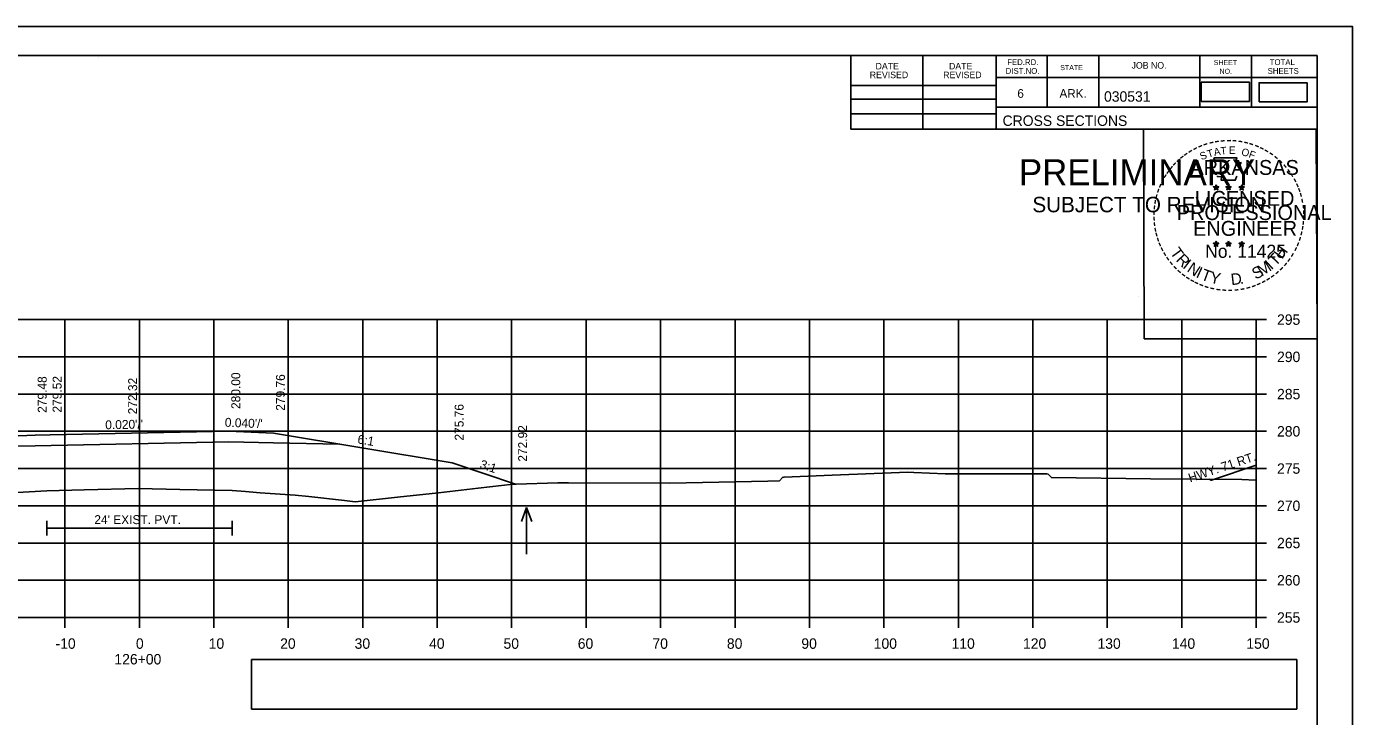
# Model space of a CAD drawing. Extents: x 285 to 4233, y -659 to 3710.
# Drawn here: x 524.1 to 702.2, y 1376.9 to 1469.5 of the extents above; entities that cross this region are included whole.
import ezdxf

# ---------------------------------------------------------------- set-up
doc = ezdxf.new("R2010")
doc.units = 0
for name, color, linetype in [('R_Alt Surface', 7, 'Continuous'), ('R_Axis', 7, 'Continuous'), ('R_Axis Annot', 7, 'Continuous'), ('R_Border', 7, 'Continuous'), ('R_Border PE', 7, 'Continuous'), ('R_Border Prem', 7, 'Continuous'), ('R_Exist Surface', 7, 'Continuous'), ('R_Fin Surface', 7, 'Continuous'), ('R_Grid', 7, 'Continuous'), ('R_No Plot', 7, 'Continuous'), ('R_Proposed Const Limits', 7, 'Continuous'), ('R_Water', 7, 'Continuous'), ('R_Water Annot', 7, 'Continuous'), ('R_Xsect Elev', 7, 'Continuous'), ('R_Xsect Slope', 7, 'Continuous')]:
    doc.layers.add(name, color=color, linetype=linetype)

msp = doc.modelspace()

# ---------------------------------------------------------------- linework, layer by layer
at = {"layer": 'R_Alt Surface'}
for points in [[(508.71, 1412.91), (517.28, 1413.08), (525.28, 1413.24), (551.28, 1413.76), (551.28, 1413.76), (557.28, 1413.64), (566.12, 1413.47)], [(526.85, 1403.17), (526.85, 1401.17)], [(526.85, 1402.17), (551.74, 1402.17)], [(551.74, 1403.17), (551.74, 1401.17)]]:
    msp.add_lwpolyline(points, dxfattribs=at)
at = {"layer": 'R_Axis'}
for p, q in [((689.28, 1390.18), (689.28, 1430.18)), ((690.68, 1430.18), (689.28, 1430.18)), ((690.68, 1425.18), (689.28, 1425.18)), ((690.68, 1420.18), (689.28, 1420.18)), ((690.68, 1415.18), (689.28, 1415.18)), ((690.68, 1410.18), (689.28, 1410.18)), ((690.68, 1405.18), (689.28, 1405.18)), ((690.68, 1400.18), (689.28, 1400.18)), ((690.68, 1395.18), (689.28, 1395.18)), ((389.28, 1390.18), (689.28, 1390.18)), ((529.28, 1388.78), (529.28, 1390.18)), ((539.28, 1388.78), (539.28, 1390.18)), ((549.28, 1388.78), (549.28, 1390.18)), ((559.28, 1388.78), (559.28, 1390.18)), ((569.28, 1388.78), (569.28, 1390.18)), ((579.28, 1388.78), (579.28, 1390.18)), ((589.28, 1388.78), (589.28, 1390.18)), ((599.28, 1388.78), (599.28, 1390.18)), ((609.28, 1388.78), (609.28, 1390.18)), ((619.28, 1388.78), (619.28, 1390.18)), ((629.28, 1388.78), (629.28, 1390.18)), ((639.28, 1388.78), (639.28, 1390.18)), ((649.28, 1388.78), (649.28, 1390.18)), ((659.28, 1388.78), (659.28, 1390.18)), ((669.28, 1388.78), (669.28, 1390.18)), ((679.28, 1388.78), (679.28, 1390.18)), ((689.28, 1388.78), (689.28, 1390.18)), ((690.68, 1390.18), (689.28, 1390.18))]:
    msp.add_line(p, q, dxfattribs=at)
at = {"layer": 'R_Axis Annot'}
for points in [[(681.91, 1459.49), (688.36, 1459.49), (688.36, 1462.05), (681.91, 1462.05)], [(689.66, 1459.42), (696.12, 1459.42), (696.12, 1461.98), (689.66, 1461.98)], [(554.36, 1377.88), (694.72, 1377.88), (694.72, 1384.53), (554.36, 1384.53)]]:
    msp.add_lwpolyline(points, close=True, dxfattribs=at)
at = {"layer": 'R_Border'}
for p, q in [((381.28, 1465.64), (697.46, 1465.64)), ((533.8, 1465.38), (533.8, 1465.38)), ((533.8, 1465.38), (533.8, 1465.38)), ((634.82, 1455.76), (634.82, 1465.64)), ((644.5, 1455.76), (644.5, 1465.64)), ((654.36, 1465.64), (654.36, 1455.76)), ((661.2, 1465.64), (661.2, 1458.7)), ((668.14, 1465.64), (668.14, 1458.7)), ((681.72, 1465.64), (681.72, 1458.7)), ((688.66, 1465.64), (688.66, 1458.7)), ((697.46, 1260.18), (697.46, 1465.64)), ((697.46, 1462.7), (654.36, 1462.7)), ((697.46, 1462.72), (697.46, 1462.72)), ((634.82, 1461.62), (654.36, 1461.62)), ((634.82, 1459.76), (654.36, 1459.76)), ((697.46, 1458.7), (654.36, 1458.7)), ((657.32, 1458.7), (697.46, 1458.7)), ((634.82, 1457.82), (654.36, 1457.82)), ((697.46, 1455.76), (634.82, 1455.76))]:
    msp.add_line(p, q, dxfattribs=at)
at = {"layer": 'R_Border PE'}
for p, q in [((683.54, 1448.02), (683.89, 1447.9)), ((683.54, 1448.02), (683.8, 1447.97)), ((683.54, 1448.02), (683.78, 1447.89)), ((683.68, 1447.61), (683.89, 1447.9)), ((683.68, 1447.61), (683.8, 1447.85)), ((683.89, 1448.27), (683.85, 1448.02)), ((683.89, 1447.9), (683.89, 1448.27)), ((683.89, 1448.27), (683.94, 1448.02)), ((684.24, 1448.02), (683.89, 1447.9)), ((684.11, 1447.61), (683.89, 1447.9)), ((684.24, 1448.02), (683.95, 1447.97)), ((684.11, 1447.61), (683.97, 1447.9)), ((684.24, 1448.02), (684.04, 1447.91)), ((685.21, 1448.02), (685.56, 1447.9)), ((685.21, 1448.02), (685.47, 1447.97)), ((685.21, 1448.02), (685.45, 1447.89)), ((685.35, 1447.61), (685.56, 1447.9)), ((685.35, 1447.61), (685.47, 1447.85)), ((685.56, 1448.27), (685.52, 1448.02)), ((685.56, 1447.9), (685.56, 1448.27)), ((685.56, 1448.27), (685.61, 1448.02)), ((685.91, 1448.02), (685.56, 1447.9)), ((685.78, 1447.61), (685.56, 1447.9)), ((685.91, 1448.02), (685.62, 1447.97)), ((685.78, 1447.61), (685.64, 1447.9)), ((685.91, 1448.02), (685.71, 1447.91)), ((686.98, 1448), (687.33, 1447.89)), ((686.98, 1448), (687.23, 1447.96)), ((686.98, 1448), (687.22, 1447.88)), ((687.11, 1447.6), (687.33, 1447.89)), ((687.33, 1448.26), (687.29, 1448.01)), ((687.33, 1447.89), (687.33, 1448.26)), ((687.33, 1448.26), (687.38, 1448.01)), ((687.67, 1448), (687.33, 1447.89)), ((687.54, 1447.6), (687.33, 1447.89)), ((687.67, 1448), (687.39, 1447.95)), ((687.54, 1447.6), (687.4, 1447.89)), ((687.67, 1448), (687.47, 1447.9)), ((683.68, 1447.61), (683.89, 1447.82)), ((684.11, 1447.61), (683.89, 1447.82)), ((685.35, 1447.61), (685.56, 1447.82)), ((685.78, 1447.61), (685.56, 1447.82)), ((687.11, 1447.6), (687.24, 1447.84)), ((687.11, 1447.6), (687.33, 1447.81)), ((687.54, 1447.6), (687.33, 1447.81)), ((683.54, 1440.44), (683.89, 1440.33)), ((683.54, 1440.44), (683.79, 1440.4)), ((683.54, 1440.44), (683.78, 1440.32)), ((683.67, 1440.03), (683.89, 1440.33)), ((683.67, 1440.03), (683.8, 1440.28)), ((683.67, 1440.03), (683.89, 1440.25)), ((683.89, 1440.7), (683.85, 1440.44)), ((683.89, 1440.33), (683.89, 1440.7)), ((683.89, 1440.7), (683.94, 1440.45)), ((684.24, 1440.44), (683.89, 1440.33)), ((684.1, 1440.03), (683.89, 1440.33)), ((684.1, 1440.03), (683.89, 1440.25)), ((684.24, 1440.44), (683.95, 1440.39)), ((684.1, 1440.03), (683.97, 1440.33)), ((684.24, 1440.44), (684.03, 1440.34)), ((685.21, 1440.44), (685.56, 1440.33)), ((685.21, 1440.44), (685.46, 1440.4)), ((685.21, 1440.44), (685.45, 1440.32)), ((685.34, 1440.03), (685.56, 1440.33)), ((685.34, 1440.03), (685.47, 1440.28)), ((685.34, 1440.03), (685.56, 1440.25)), ((685.56, 1440.7), (685.52, 1440.44)), ((685.56, 1440.33), (685.56, 1440.7)), ((685.56, 1440.7), (685.61, 1440.45)), ((685.91, 1440.44), (685.56, 1440.33)), ((685.77, 1440.03), (685.56, 1440.33)), ((685.77, 1440.03), (685.56, 1440.25)), ((685.91, 1440.44), (685.62, 1440.39)), ((685.77, 1440.03), (685.63, 1440.33)), ((685.91, 1440.44), (685.7, 1440.34)), ((686.98, 1440.43), (687.33, 1440.32)), ((686.98, 1440.43), (687.23, 1440.39)), ((686.98, 1440.43), (687.21, 1440.31)), ((687.11, 1440.02), (687.33, 1440.32)), ((687.11, 1440.02), (687.24, 1440.27)), ((687.11, 1440.02), (687.32, 1440.24)), ((687.33, 1440.69), (687.28, 1440.43)), ((687.54, 1440.02), (687.32, 1440.24)), ((687.33, 1440.32), (687.33, 1440.69)), ((687.33, 1440.69), (687.37, 1440.44)), ((687.67, 1440.43), (687.33, 1440.32)), ((687.54, 1440.02), (687.33, 1440.32)), ((687.67, 1440.43), (687.39, 1440.38)), ((687.54, 1440.02), (687.4, 1440.32)), ((687.67, 1440.43), (687.47, 1440.33))]:
    msp.add_line(p, q, dxfattribs=at)
for points in [[(683.59, 1451.89), (683.85, 1451.07)], [(687.1, 1450.97), (687.24, 1451.26), (686.55, 1451.23), (686.7, 1451.89), (683.59, 1451.89)], [(683.89, 1448.27), (684.11, 1447.61), (683.54, 1448.02), (684.24, 1448.02), (683.68, 1447.61), (683.89, 1448.27)], [(684.08, 1449.47), (684.08, 1449.38), (684.64, 1449.36), (684.59, 1448.89), (686.46, 1448.89), (686.66, 1449.43)], [(685.56, 1448.27), (685.78, 1447.61), (685.21, 1448.02), (685.91, 1448.02), (685.35, 1447.61), (685.56, 1448.27)], [(687.33, 1448.26), (687.54, 1447.6), (686.98, 1448), (687.67, 1448), (687.11, 1447.6), (687.33, 1448.26)], [(683.89, 1440.7), (684.1, 1440.03), (683.54, 1440.44), (684.24, 1440.44), (683.67, 1440.03), (683.89, 1440.7)], [(685.56, 1440.7), (685.77, 1440.03), (685.21, 1440.44), (685.91, 1440.44), (685.34, 1440.03), (685.56, 1440.7)], [(687.33, 1440.69), (687.54, 1440.02), (686.98, 1440.43), (687.67, 1440.43), (687.11, 1440.02), (687.33, 1440.69)]]:
    msp.add_lwpolyline(points, dxfattribs=at)
for centre, radius in [((683.89, 1447.9), 0.172), ((683.89, 1447.9), 0.145), ((683.89, 1447.9), 0.116), ((683.89, 1447.9), 0.0991), ((683.89, 1447.9), 0.0747), ((683.89, 1447.9), 0.0495), ((683.89, 1447.9), 0.0296), ((685.56, 1447.9), 0.172), ((685.56, 1447.9), 0.145), ((685.56, 1447.9), 0.116), ((685.56, 1447.9), 0.0991), ((685.56, 1447.9), 0.0747), ((685.56, 1447.9), 0.0495), ((685.56, 1447.9), 0.0296), ((687.33, 1447.89), 0.172), ((687.33, 1447.89), 0.145), ((687.33, 1447.89), 0.116), ((687.33, 1447.89), 0.0991), ((687.33, 1447.89), 0.0747), ((687.33, 1447.89), 0.0495), ((687.33, 1447.89), 0.0296), ((683.89, 1440.33), 0.172), ((683.89, 1440.33), 0.145), ((683.89, 1440.33), 0.116), ((683.89, 1440.33), 0.0991), ((683.89, 1440.33), 0.0747), ((683.89, 1440.33), 0.0495), ((683.89, 1440.33), 0.0296), ((685.56, 1440.33), 0.172), ((685.56, 1440.33), 0.145), ((685.56, 1440.33), 0.116), ((685.56, 1440.33), 0.0991), ((685.56, 1440.33), 0.0747), ((685.56, 1440.33), 0.0495), ((685.56, 1440.33), 0.0296), ((687.32, 1440.32), 0.172), ((687.32, 1440.32), 0.145), ((687.32, 1440.32), 0.116), ((687.32, 1440.32), 0.0991), ((687.32, 1440.32), 0.0747), ((687.32, 1440.32), 0.0495), ((687.32, 1440.32), 0.0296)]:
    msp.add_circle(centre, radius, dxfattribs=at)
at = {"layer": 'R_Exist Surface'}
msp.add_lwpolyline([(521.32, 1406.88), (526.85, 1407.17), (531.87, 1407.31), (539.17, 1407.51), (544.72, 1407.39), (551.74, 1407.24), (553.52, 1407.1), (555.5, 1406.94), (560.21, 1406.59), (562.06, 1406.42), (566.84, 1405.87), (568.25, 1405.7), (573.96, 1406.33), (579.47, 1406.93), (584.8, 1407.55), (589.47, 1408.09), (589.89, 1408.1), (595.49, 1408.26), (596.92, 1408.25), (610.53, 1408.23), (623.67, 1408.49), (625.25, 1408.52), (625.27, 1408.55), (625.65, 1408.99), (625.86, 1409.04), (625.89, 1409.04), (632.34, 1409.29), (642.5, 1409.68), (643.31, 1409.65), (647.51, 1409.49), (660.23, 1409.47), (661.13, 1409.47), (661.16, 1409.47), (661.36, 1409.41), (661.64, 1409.1), (661.77, 1408.97), (675.1, 1408.82), (687.37, 1408.69), (689.17, 1408.63), (689.28, 1408.63)], dxfattribs=at)
at = {"layer": 'R_Fin Surface'}
for points in [[(469.1, 1404.15), (472.9, 1402.88), (497.28, 1411.01), (517.28, 1414.34), (525.28, 1414.66), (527.28, 1414.7), (551.28, 1415.18), (557.28, 1414.94), (581.28, 1410.94), (589.81, 1408.1)], [(682.97, 1408.74), (683.25, 1408.64), (683.27, 1408.64), (689.28, 1410.64)]]:
    msp.add_lwpolyline(points, dxfattribs=at)
at = {"layer": 'R_Grid'}
for p, q in [((389.28, 1430.18), (689.28, 1430.18)), ((529.28, 1390.18), (529.28, 1430.18)), ((539.28, 1390.18), (539.28, 1430.18)), ((549.28, 1390.18), (549.28, 1430.18)), ((559.28, 1390.18), (559.28, 1430.18)), ((569.28, 1390.18), (569.28, 1430.18)), ((579.28, 1390.18), (579.28, 1430.18)), ((589.28, 1390.18), (589.28, 1430.18)), ((599.28, 1390.18), (599.28, 1430.18)), ((609.28, 1390.18), (609.28, 1430.18)), ((619.28, 1390.18), (619.28, 1430.18)), ((629.28, 1390.18), (629.28, 1430.18)), ((639.28, 1390.18), (639.28, 1430.18)), ((649.28, 1390.18), (649.28, 1430.18)), ((659.28, 1390.18), (659.28, 1430.18)), ((669.28, 1390.18), (669.28, 1430.18)), ((679.28, 1390.18), (679.28, 1430.18)), ((689.28, 1390.18), (689.28, 1430.18)), ((389.28, 1425.18), (689.28, 1425.18)), ((389.28, 1420.18), (689.28, 1420.18)), ((389.28, 1415.18), (689.28, 1415.18)), ((389.28, 1410.18), (689.28, 1410.18)), ((389.28, 1405.18), (689.28, 1405.18)), ((389.28, 1400.18), (689.28, 1400.18)), ((389.28, 1395.18), (689.28, 1395.18)), ((389.28, 1390.18), (689.28, 1390.18))]:
    msp.add_line(p, q, dxfattribs=at)
at = {"layer": 'R_No Plot'}
for p, q in [((368.88, 1469.54), (702.21, 1469.54)), ((673.49, 1433.3), (673.49, 1433.3))]:
    msp.add_line(p, q, dxfattribs=at)
for points in [[(368.87, 1469.54), (702.21, 1469.54), (702.21, 1256.2), (368.87, 1256.2)], [(615.2, 1465.64), (634.82, 1465.64), (634.82, 1455.76), (650.93, 1455.76), (674.13, 1455.76), (674.25, 1427.6), (697.46, 1427.6), (697.46, 1260.18), (381.28, 1260.18), (381.28, 1465.64)], [(674.13, 1455.76), (697.34, 1455.76), (697.46, 1427.6), (674.25, 1427.6)]]:
    msp.add_lwpolyline(points, close=True, dxfattribs=at)
at = {"layer": 'R_Proposed Const Limits'}
for points in [[(527.28, 1414.7), (527.28, 1414.7), (527.28, 1414.7)], [(551.28, 1415.18), (551.28, 1415.18), (551.28, 1415.18)], [(589.82, 1408.09), (589.81, 1408.1), (589.8, 1408.1), (589.79, 1408.1)]]:
    msp.add_lwpolyline(points, dxfattribs=at)
at = {"layer": 'R_Water Annot'}
for p, q in [((591.29, 1404.97), (590.59, 1403.05)), ((591.29, 1398.69), (591.29, 1404.97)), ((591.29, 1404.97), (591.99, 1403.05))]:
    msp.add_line(p, q, dxfattribs=at)
at = {"layer": 'R_Xsect Elev'}
msp.add_line((539.28, 1407.5), (539.28, 1423.25), dxfattribs=at)

# ---------------------------------------------------------------- texts
at = {"layer": 'R_Axis Annot'}
for s, p in [('295', (692.08, 1429.48)), ('290', (692.08, 1424.48)), ('285', (692.08, 1419.48)), ('280', (692.08, 1414.48)), ('275', (692.08, 1409.48)), ('270', (692.08, 1404.48)), ('265', (692.08, 1399.48)), ('260', (692.08, 1394.48)), ('255', (692.08, 1389.48)), ('-10', (528.02, 1385.98)), ('0', (538.82, 1385.98)), ('10', (548.59, 1385.98)), ('20', (558.19, 1385.98)), ('30', (568.19, 1385.98)), ('40', (578.19, 1385.98)), ('50', (588.19, 1385.98)), ('60', (598.16, 1385.98)), ('70', (608.19, 1385.98)), ('80', (618.19, 1385.98)), ('90', (628.19, 1385.98)), ('100', (637.91, 1385.98)), ('110', (648.36, 1385.98)), ('120', (657.96, 1385.98)), ('130', (667.96, 1385.98)), ('140', (677.96, 1385.98)), ('150', (687.96, 1385.98)), ('126+00', (535.93, 1383.88))]:
    msp.add_text(s, height=1.4, dxfattribs=at).set_placement(p)
at = {"layer": 'R_Border'}
for s, height, p in [('DATE', 0.879, (638.16, 1463.78)), ('DATE', 0.879, (648.02, 1463.78)), ('DIST.NO.', 0.782, (655.64, 1463.18)), ('FED.RD.', 0.782, (655.84, 1464.36)), ('STATE', 0.684, (662.96, 1463.68)), ('JOB NO.', 0.879, (672.54, 1463.88)), ('SHEET', 0.684, (683.58, 1464.36)), ('SHEETS', 0.782, (690.82, 1463.18)), ('TOTAL', 0.782, (691.1, 1464.36)), ('REVISED', 0.879, (637.38, 1462.6)), ('REVISED', 0.879, (647.24, 1462.6)), ('NO.', 0.684, (684.36, 1463.18)), ('6', 1.17, (657.2, 1459.96)), ('ARK.', 1.172, (662.86, 1459.96)), ('030531', 1.4, (668.84, 1459.44)), ('CROSS SECTIONS', 1.4, (655.22, 1456.19))]:
    msp.add_text(s, height=height, rotation=360, dxfattribs=at).set_placement(p)
at = {"layer": 'R_Border PE'}
for s, height, rotation, p in [('-', 1.6, 28.7918, (681.07, 1452.43)), ('-', 1.6, 24.3072, (681.7, 1452.75)), ('-', 1.6, 19.1761, (682.33, 1453.02)), ('-', 1.6, 13.6301, (683.08, 1453.26)), ('A', 1, 11.2132, (683.68, 1452.15)), ('-', 1.6, 10.2193, (683.76, 1453.42)), ('T', 1, 6.0228, (684.53, 1452.32)), ('-', 1.6, 5.8968, (684.49, 1453.53)), ('-', 1.6, 0.1862, (685.26, 1453.61)), ('E', 1, 0.8323, (685.63, 1452.43)), ('-', 1.6, 357.743, (685.98, 1453.59)), ('-', 1.6, 352.1617, (686.73, 1453.54)), ('-', 1.6, 347.2049, (687.45, 1453.42)), ('-', 1.6, 342.3362, (688.08, 1453.27)), ('-', 1.6, 337.8551, (688.82, 1453.04)), ('-', 1.6, 334.1211, (689.45, 1452.77)), ('-', 1.6, 42.9622, (678.98, 1450.87)), ('-', 1.6, 38.9507, (679.41, 1451.29)), ('-', 1.6, 36.2317, (679.89, 1451.67)), ('-', 1.6, 34.0636, (680.47, 1452.06)), ('ARKANSAS', 2, 360, (680.44, 1449.61)), ('S', 1, 21.594, (681.94, 1451.57)), ('T', 1, 16.4036, (682.85, 1451.9)), ('O', 1, 350.4515, (687.24, 1452.22)), ('F', 1, 340.0707, (688.19, 1451.99)), ('-', 1.6, 329.6409, (690.03, 1452.49)), ('-', 1.6, 325.8627, (690.67, 1452.13)), ('-', 1.6, 320.5297, (691.28, 1451.7)), ('-', 1.6, 315.5786, (691.88, 1451.22)), ('-', 1.6, 58.0706, (677.39, 1448.82)), ('-', 1.6, 54.2325, (677.72, 1449.34)), ('-', 1.6, 50.6142, (678.13, 1449.91)), ('-', 1.6, 48.423, (678.53, 1450.4)), ('-', 1.6, 309.8797, (692.45, 1450.67)), ('-', 1.6, 306.6522, (692.97, 1450.06)), ('-', 1.4, 303.6753, (693.46, 1449.5)), ('-', 1.6, 67.7743, (676.82, 1447.59)), ('-', 1.6, 62.8713, (677.08, 1448.2)), ('DWB', 0.01, 360, (683.88, 1447.9)), ('DWB', 0.01, 360, (685.55, 1447.9)), ('DWB', 0.01, 360, (687.31, 1447.89)), ('-', 1.6, 299.6684, (693.78, 1448.89)), ('-', 1.6, 294.6628, (694.1, 1448.28)), ('-', 1.6, 290.5728, (694.36, 1447.7)), ('-', 1.6, 81.2013, (676.27, 1445.53)), ('-', 1.6, 75.461, (676.4, 1446.25)), ('-', 1.6, 72.3945, (676.6, 1446.96)), ('LICENSED', 2, 360, (681.04, 1445.46)), ('-', 1.6, 285.1233, (694.59, 1447.12)), ('-', 1.6, 280.5493, (694.79, 1446.38)), ('-', 1.6, 89.0622, (676.17, 1444.14)), ('-', 1.6, 85.1863, (676.2, 1444.84)), ('PROFESSIONAL', 2, 360, (678.61, 1443.55)), ('-', 1.6, 276.5962, (694.96, 1445.61)), ('-', 1.6, 274.3301, (695.02, 1444.89)), ('-', 1.6, 94.1959, (676.21, 1443.42)), ('-', 1.6, 98.9479, (676.28, 1442.75)), ('-', 1.6, 101.7149, (676.41, 1442.02)), ('ENGINEER', 2, 360, (680.8, 1441.43)), ('-', 1.6, 260.9953, (694.96, 1442.94)), ('-', 1.6, 263.5172, (695.03, 1443.59)), ('-', 1.6, 269.9407, (695.05, 1444.26)), ('-', 1.6, 105.4578, (676.58, 1441.42)), ('-', 1.6, 109.0874, (676.79, 1440.79)), ('-', 1.6, 252.8681, (694.67, 1441.54)), ('-', 1.6, 255.7626, (694.85, 1442.26)), ('-', 1.6, 114.0643, (677.04, 1440.2)), ('-', 1.6, 115.7289, (677.35, 1439.58)), ('-', 1.6, 120.4471, (677.71, 1438.99)), ('T', 1.54, 306.0406, (677.65, 1439.17)), ('R', 1.54, 314.005, (678.41, 1438.12)), ('No. 11425', 1.757, 360, (682.43, 1438.48)), ('DWB', 0.01, 360, (683.88, 1440.33)), ('DWB', 0.01, 360, (685.55, 1440.33)), ('DWB', 0.01, 360, (687.31, 1440.32)), ('T', 1.54, 46.6444, (691.88, 1437.26)), ('H', 1.54, 54.6088, (692.77, 1438.2)), ('-', 1.6, 239.0712, (693.79, 1439.48)), ('-', 1.6, 244.6197, (694.18, 1440.24)), ('-', 1.6, 247.8887, (694.45, 1440.86)), ('-', 1.6, 125.8934, (678.11, 1438.43)), ('-', 1.6, 130.7181, (678.57, 1437.88)), ('-', 1.6, 134.2238, (679.09, 1437.33)), ('I', 1.54, 321.9694, (679.31, 1437.19)), ('N', 1.54, 326.5002, (679.88, 1436.72)), ('I', 1.54, 335.3603, (681.09, 1435.93)), ('S', 1.54, 26.9312, (689.19, 1435.53)), ('M', 1.54, 32.6563, (690.03, 1435.94)), ('I', 1.54, 42.1136, (691.32, 1436.78)), ('-', 1.6, 225.7653, (692.48, 1437.7)), ('-', 1.6, 231.2538, (692.96, 1438.26)), ('-', 1.6, 233.8452, (693.39, 1438.83)), ('-', 1.6, 138.9338, (679.61, 1436.87)), ('-', 1.6, 144.6463, (680.17, 1436.46)), ('-', 1.6, 148.0898, (680.73, 1436.09)), ('-', 1.6, 151.5704, (681.31, 1435.77)), ('T', 1.54, 339.8912, (681.75, 1435.6)), ('Y', 1.54, 347.8556, (682.97, 1435.16)), ('D', 1.54, 6.3969, (685.95, 1434.8)), ('-', 1.6, 207.3568, (690.32, 1435.99)), ('-', 1.6, 212.2491, (690.87, 1436.33)), ('-', 1.6, 215.7363, (691.41, 1436.72)), ('-', 1.6, 221.0851, (691.96, 1437.19)), ('-', 1.6, 154.6002, (681.83, 1435.52)), ('-', 1.6, 158.5612, (682.46, 1435.27)), ('-', 1.6, 162.7983, (683.14, 1435.05)), ('-', 1.6, 167.5555, (683.86, 1434.89)), ('-', 1.6, 173.1155, (684.63, 1434.78)), ('-', 1.6, 176.5183, (685.38, 1434.73)), ('-', 1.6, 181.5918, (686.12, 1434.75)), ('-', 1.6, 185.8167, (686.93, 1434.82)), ('-', 1.6, 191.2858, (687.67, 1434.95)), ('.', 1.54, 13.7642, (687.14, 1434.93)), ('-', 1.6, 195.4743, (688.4, 1435.15)), ('-', 1.6, 200.7184, (689.07, 1435.39)), ('-', 1.6, 204.2516, (689.69, 1435.67))]:
    msp.add_text(s, height=height, rotation=rotation, dxfattribs=at).set_placement(p)
at = {"layer": 'R_Border Prem'}
for s, height, p in [('PRELIMINARY', 3.5, (657.41, 1448.22)), ('DWB', 0.01, (658.16, 1450.07)), ('SUBJECT TO REVISION', 2.0751, (659.22, 1444.59))]:
    msp.add_text(s, height=height, rotation=360, dxfattribs=at).set_placement(p)
at = {"layer": 'R_Water'}
msp.add_text('HWY. 71 RT.', height=1.2, rotation=18.4313, dxfattribs=at).set_placement((680.4, 1408.31))
msp.add_text("24' EXIST. PVT.", height=1.2, dxfattribs=at).set_placement((533.23, 1402.72))
at = {"layer": 'R_Xsect Elev'}
for s, p in [('280.00', (552.83, 1418.18)), ('279.48', (526.83, 1417.66)), ('279.52', (528.83, 1417.7)), ('272.32', (538.98, 1417.46)), ('279.76', (558.83, 1417.94)), ('275.76', (582.83, 1413.94)), ('272.92', (591.36, 1411.1))]:
    msp.add_text(s, height=1.2, rotation=90, dxfattribs=at).set_placement(p)
at = {"layer": 'R_Xsect Slope'}
for s, rotation, p in [("0.020'/'", 1.1458, (534.71, 1415.45)), ("0.040'/'", 357.7094, (550.74, 1415.8)), ('6:1', 350.5377, (568.51, 1413.57)), ('3:1', 341.5651, (584.91, 1410.26))]:
    msp.add_text(s, height=1.2, rotation=rotation, dxfattribs=at).set_placement(p)

doc.saveas('drawing.dxf')
